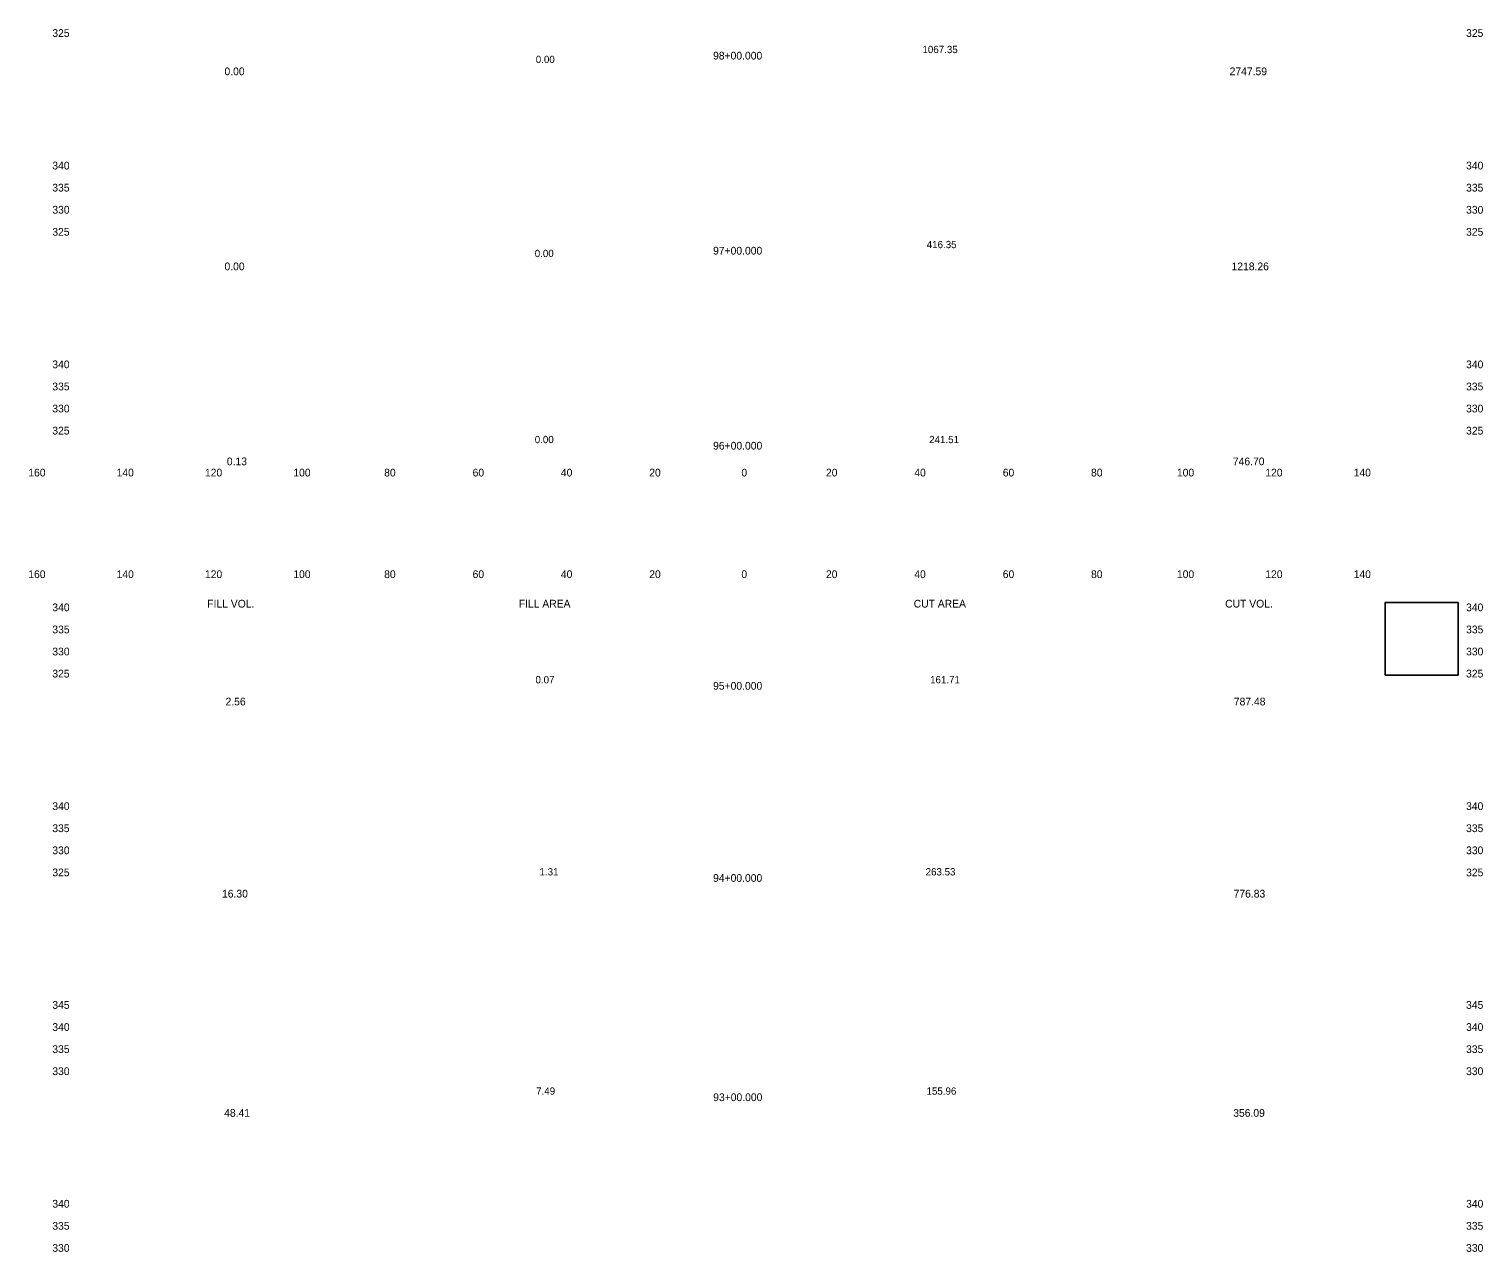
# Model space of a CAD drawing. Extents: x 21477 to 21806, y 6470 to 11049.
# Drawn here: x 21477.1 to 21806.1, y 6754.8 to 7031.6 of the extents above; entities that cross this region are included whole.
import ezdxf

# ---------------------------------------------------------------- set-up
doc = ezdxf.new("R2010")
doc.units = 0
for name, color, linetype in [('SHEET_CONSULTANT_STAMP', 7, 'Continuous'), ('XS_SHEET_EW_TX_AREA', 7, 'Continuous'), ('XS_SHEET_EW_TX_VOLUME', 7, 'Continuous'), ('XS_SHEET_LABELS_ELEVATION', 7, 'Continuous'), ('XS_SHEET_LABELS_OFFSET', 7, 'Continuous'), ('XS_SHEET_LABELS_STATION', 7, 'Continuous'), ('XS_SHEET_TX', 7, 'Continuous')]:
    doc.layers.add(name, color=color, linetype=linetype)

msp = doc.modelspace()

# ---------------------------------------------------------------- linework, layer by layer
at = {"layer": 'SHEET_CONSULTANT_STAMP'}
msp.add_lwpolyline([(21784.04, 6885.34), (21800.54, 6885.34), (21800.54, 6901.84), (21784.04, 6901.84)], close=True, dxfattribs=at)

# ---------------------------------------------------------------- texts
at = {"layer": 'XS_SHEET_EW_TX_AREA'}
for s, p in [(' 1067.35 ', (21678.68, 7026.17)), (' 0.00 ', (21591.16, 7023.92)), (' 416.35 ', (21679.65, 6982.02)), (' 0.00 ', (21590.92, 6980)), (' 0.00 ', (21590.92, 6937.88)), (' 241.51 ', (21680.2, 6937.88)), (' 0.07 ', (21591.09, 6883.52)), (' 161.71 ', (21680.41, 6883.52)), (' 1.31 ', (21592, 6840.03)), (' 263.53 ', (21679.4, 6840.03)), (' 7.49 ', (21591.24, 6790.4)), (' 155.96 ', (21679.6, 6790.4))]:
    msp.add_text(s, height=1.65, dxfattribs=at).set_placement(p)
at = {"layer": 'XS_SHEET_EW_TX_VOLUME'}
for s, p in [(' 0.00 ', (21520.66, 7021.17)), (' 2747.59 ', (21748.17, 7021.17)), (' 0.00 ', (21520.66, 6977.02)), (' 1218.26 ', (21748.6, 6977.02)), (' 0.13 ', (21521.19, 6932.88)), (' 746.70 ', (21748.9, 6932.88)), (' 2.56 ', (21520.9, 6878.52)), (' 787.48 ', (21749.12, 6878.52)), (' 16.30 ', (21520.1, 6835.03)), (' 776.83 ', (21749.07, 6835.03)), (' 48.41 ', (21520.59, 6785.4)), (' 356.09 ', (21748.98, 6785.4))]:
    msp.add_text(s, height=1.75, dxfattribs=at).set_placement(p)
at = {"layer": 'XS_SHEET_LABELS_ELEVATION'}
for s, p in [('  325  ', (21481.04, 7029.84)), ('  325  ', (21801.04, 7029.84)), ('  340  ', (21481.04, 6999.84)), ('  340  ', (21801.04, 6999.84)), ('  335  ', (21481.04, 6994.84)), ('  335  ', (21801.04, 6994.84)), ('  330  ', (21481.04, 6989.84)), ('  330  ', (21801.04, 6989.84)), ('  325  ', (21481.04, 6984.84)), ('  325  ', (21801.04, 6984.84)), ('  340  ', (21481.04, 6954.84)), ('  340  ', (21801.04, 6954.84)), ('  335  ', (21481.04, 6949.84)), ('  335  ', (21801.04, 6949.84)), ('  330  ', (21481.04, 6944.84)), ('  330  ', (21801.04, 6944.84)), ('  325  ', (21481.04, 6939.84)), ('  325  ', (21801.04, 6939.84)), ('  340  ', (21481.04, 6899.84)), ('  340  ', (21801.04, 6899.84)), ('  335  ', (21481.04, 6894.84)), ('  335  ', (21801.04, 6894.84)), ('  330  ', (21481.04, 6889.84)), ('  330  ', (21801.04, 6889.84)), ('  325  ', (21481.04, 6884.84)), ('  325  ', (21801.04, 6884.84)), ('  340  ', (21481.04, 6854.84)), ('  340  ', (21801.04, 6854.84)), ('  335  ', (21481.04, 6849.84)), ('  335  ', (21801.04, 6849.84)), ('  330  ', (21481.04, 6844.84)), ('  330  ', (21801.04, 6844.84)), ('  325  ', (21481.04, 6839.84)), ('  325  ', (21801.04, 6839.84)), ('  345  ', (21481.04, 6809.84)), ('  345  ', (21801.04, 6809.84)), ('  340  ', (21481.04, 6804.84)), ('  340  ', (21801.04, 6804.84)), ('  335  ', (21481.04, 6799.84)), ('  335  ', (21801.04, 6799.84)), ('  330  ', (21481.04, 6794.84)), ('  330  ', (21801.04, 6794.84)), ('  340  ', (21481.04, 6764.84)), ('  340  ', (21801.04, 6764.84)), ('  335  ', (21481.04, 6759.84)), ('  335  ', (21801.04, 6759.84)), ('  330  ', (21481.04, 6754.84)), ('  330  ', (21801.04, 6754.84))]:
    msp.add_text(s, height=1.75, dxfattribs=at).set_placement(p)
at = {"layer": 'XS_SHEET_LABELS_OFFSET'}
for s, p in [('  160  ', (21475.6, 6930.34)), ('  140  ', (21495.59, 6930.34)), ('  120  ', (21515.59, 6930.34)), ('  100  ', (21535.59, 6930.34)), ('  80  ', (21556.15, 6930.34)), ('  60  ', (21576.17, 6930.34)), ('  40  ', (21596.15, 6930.34)), ('  20  ', (21616.15, 6930.34)), ('  0  ', (21637.01, 6930.34)), ('  0  ', (21637.01, 6930.34)), ('  20  ', (21656.15, 6930.34)), ('  40  ', (21676.15, 6930.34)), ('  60  ', (21696.17, 6930.34)), ('  80  ', (21716.15, 6930.34)), ('  100  ', (21735.59, 6930.34)), ('  120  ', (21755.59, 6930.34)), ('  140  ', (21775.59, 6930.34)), ('  160  ', (21475.6, 6907.34)), ('  140  ', (21495.59, 6907.34)), ('  120  ', (21515.59, 6907.34)), ('  100  ', (21535.59, 6907.34)), ('  80  ', (21556.15, 6907.34)), ('  60  ', (21576.17, 6907.34)), ('  40  ', (21596.15, 6907.34)), ('  20  ', (21616.15, 6907.34)), ('  0  ', (21637.01, 6907.34)), ('  0  ', (21637.01, 6907.34)), ('  20  ', (21656.15, 6907.34)), ('  40  ', (21676.15, 6907.34)), ('  60  ', (21696.17, 6907.34)), ('  80  ', (21716.15, 6907.34)), ('  100  ', (21735.59, 6907.34)), ('  120  ', (21755.59, 6907.34)), ('  140  ', (21775.59, 6907.34))]:
    msp.add_text(s, height=1.75, dxfattribs=at).set_placement(p)
at = {"layer": 'XS_SHEET_LABELS_STATION'}
for s, p in [('  98+00.000  ', (21630.6, 7024.72)), ('  97+00.000  ', (21630.6, 6980.57)), ('  96+00.000  ', (21630.61, 6936.43)), ('  95+00.000  ', (21630.6, 6882.07)), ('  94+00.000  ', (21630.6, 6838.58)), ('  93+00.000  ', (21630.63, 6788.95))]:
    msp.add_text(s, height=1.75, dxfattribs=at).set_placement(p)
at = {"layer": 'XS_SHEET_TX'}
for s, p in [('FILL VOL.', (21517.41, 6900.67)), ('FILL AREA', (21587.92, 6900.67)), ('CUT AREA', (21677.31, 6900.67)), ('CUT VOL.', (21747.8, 6900.67))]:
    msp.add_text(s, height=1.75, dxfattribs=at).set_placement(p)

doc.saveas('drawing.dxf')
